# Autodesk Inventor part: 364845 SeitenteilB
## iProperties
Company: Mayer & Müller AG Schaltgeräte
Created: 2011-07
Part Number: 364845 SeitenteilB
Material: 1.0120
Document SubType Name: Modeling
Designer: I.Baliuc
Manufacturer: Standard
Standards Organization: Custom
Description: Seitenteil, Trenner
Cost Center: 5,196 kg
Authority: 661896 mm^3
Density: 7.85 g/cm^3
HalbzeugNorm: DIN 174
Zweck: HSLT / HSE - Standardseite
Abmessung: Fl. 120x12-170
SaveDate: 2006-10-28
SaveTime: 20:23
TotalMass: 5,196 kg
TotalVolume: 661896 mm^3
Author: GDK-8530w-2
Revision Number: 364845
Keywords: 380125
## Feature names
1. Extrusion2
2. Bohrung_Ø13 [Hole]
3. Bohrung2 [Hole]
4. Bohrung3 [Hole]
5. Bohrung_M8_01 [Hole]
6. Bohrung_M8_02 [Hole]
7. Bohrung_M6 [Hole]
8. Bohrung_M5 [Hole]
9. Neue Bohrung (zusätzlich) [Rectangular Pattern]
